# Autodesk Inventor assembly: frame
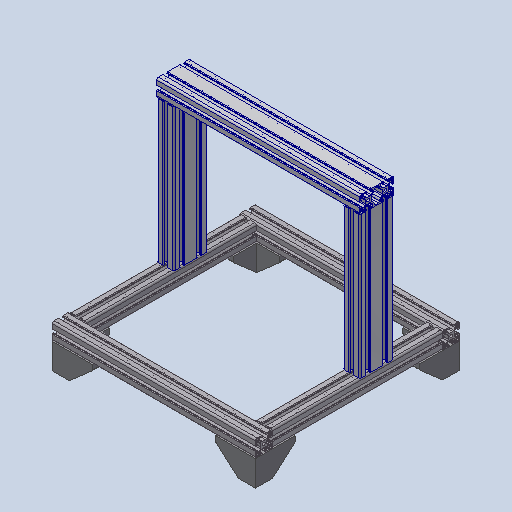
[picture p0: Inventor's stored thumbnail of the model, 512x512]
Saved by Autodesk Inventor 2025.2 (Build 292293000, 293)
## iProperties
Created: 2025-04
Part Number: frame
Material: Generisch
Document SubType Name: Assembly
Designer: BennF
Author: BennF
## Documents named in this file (7)
- C:\Users\BennF\Nextcloud\Benutzer\Benedikt\FabAcademy\week12\CAD\frame\frame.iam
- C:\Users\BennF\Nextcloud\Benutzer\Benedikt\FabAcademy\week12\CAD\frame\profile_3030_258.ipt
- C:\Users\BennF\Nextcloud\Benutzer\Benedikt\FabAcademy\week12\CAD\frame\profile_3030x300.ipt
- C:\Users\BennF\Nextcloud\Benutzer\Benedikt\FabAcademy\week12\CAD\frame\profile_6030x250.ipt
- C:\Users\BennF\Nextcloud\Benutzer\Benedikt\FabAcademy\week12\CAD\frame\profile_6030x358.ipt
- C:\Users\BennF\Nextcloud\Benutzer\Benedikt\FabAcademy\week12\CAD\frame\feet.ipt
- C:\Users\BennF\Nextcloud\Benutzer\Benedikt\FabAcademy\week12\CAD\frame\rubber_feet.ipt
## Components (15 placed, 6 different names)
1. profile_3030_258:1 — Mate:1, Mate:2, Flush:1, Flush:3, Flush:4, Flush:10, Mate:7, Mate:8, Mate:9, Mate:10, Flush:13, Flush:15
2. profile_3030_258:2 — Mate:3, Flush:2, Flush:5, Flush:6, Flush:18, Flush:19
3. profile_3030x300:1
4. profile_3030x300:2 — Mate:1, Flush:1, Flush:2, Flush:4, Flush:5, Mate:5, Flush:7, Flush:16, Flush:17
5. profile_6030x250:1 — Mate:4, Flush:8, Flush:9, Flush:10, Mate:6
6. profile_6030x250:2 — Mate:5, Flush:7, Flush:9, Flush:11, Flush:12
7. profile_6030x358:1 — Mate:6, Flush:11, Flush:12
8. feet:1 — Mate:7, Flush:13, Flush:14, Insert:1
9. feet:2 — Mate:8, Flush:15, Flush:16, Insert:2
10. feet:3 — Mate:9, Flush:17, Flush:18, Insert:3
11. feet:4 — Mate:10, Flush:19, Flush:20, Insert:4
12. rubber_feet:1 — Insert:1
13. rubber_feet:2 — Insert:2
14. rubber_feet:3 — Insert:3
15. rubber_feet:4 — Insert:4
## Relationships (34: Flush 20, Mate 10, Insert 4)
- Mate:1: profile_3030_258:1 ↔ profile_3030x300:2
- Mate:2: profile_3030_258:1
- Mate:3: profile_3030_258:2
- Flush:1: profile_3030_258:1 ↔ profile_3030x300:2
- Flush:2: profile_3030_258:2 ↔ profile_3030x300:2
- Flush:3: profile_3030_258:1
- Flush:4: profile_3030_258:1 ↔ profile_3030x300:2
- Flush:5: profile_3030_258:2 ↔ profile_3030x300:2
- Flush:6: profile_3030_258:2
- Mate:4: profile_6030x250:1
- Mate:5: profile_3030x300:2 ↔ profile_6030x250:2
- Flush:7: profile_3030x300:2 ↔ profile_6030x250:2
- Flush:8: profile_6030x250:1
- Flush:9: profile_6030x250:1 ↔ profile_6030x250:2
- Flush:10: profile_3030_258:1 ↔ profile_6030x250:1
- Mate:6: profile_6030x250:1 ↔ profile_6030x358:1
- Flush:11: profile_6030x250:2 ↔ profile_6030x358:1
- Flush:12: profile_6030x250:2 ↔ profile_6030x358:1
- Mate:7: profile_3030_258:1 ↔ feet:1
- Mate:8: profile_3030_258:1 ↔ feet:2
- Mate:9: profile_3030_258:1 ↔ feet:3
- Mate:10: profile_3030_258:1 ↔ feet:4
- Flush:13: profile_3030_258:1 ↔ feet:1
- Flush:14: feet:1
- Flush:15: profile_3030_258:1 ↔ feet:2
- Flush:16: profile_3030x300:2 ↔ feet:2
- Flush:17: profile_3030x300:2 ↔ feet:3
- Flush:18: profile_3030_258:2 ↔ feet:3
- Flush:19: profile_3030_258:2 ↔ feet:4
- Flush:20: feet:4
- Insert:1: feet:1 ↔ rubber_feet:1
- Insert:2: feet:2 ↔ rubber_feet:2
- Insert:3: feet:3 ↔ rubber_feet:3
- Insert:4: feet:4 ↔ rubber_feet:4
